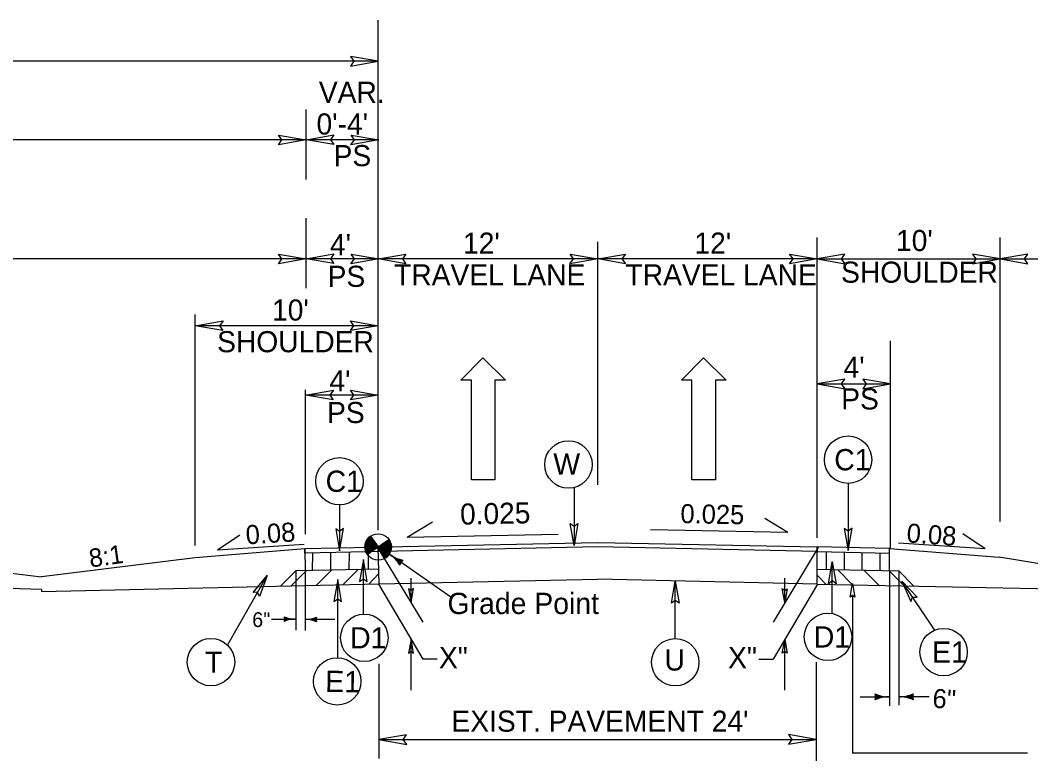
# Model space of a CAD drawing. Extents: x 2176024 to 2177225, y 75947 to 76635.
# Drawn here: x 2177049.6 to 2177104.9, y 76542.3 to 76582.8 of the extents above; entities that cross this region are included whole.
import ezdxf

# ---------------------------------------------------------------- set-up
doc = ezdxf.new("R2010")
doc.units = 0
for name, color, linetype in [('Exist XS Ground Line', 7, 'Continuous'), ('Old_Level_1', 7, 'Continuous'), ('Old_Level_11', 7, 'Continuous'), ('Old_Level_4', 7, 'Continuous'), ('Prop Dimension', 7, 'Continuous'), ('Typical Curb CELL', 7, 'Continuous'), ('Typical Grade Point Symbol CELL', 7, 'Continuous'), ('Typical Pavement Slope CELL', 7, 'Continuous'), ('Typical Pavement Slope Information CELL', 7, 'Continuous'), ('Typical Shoulder Slope CELL', 7, 'Continuous'), ('Typical Slope Point Local CELL', 7, 'Continuous'), ('Typical Terminator CELL', 7, 'Continuous'), ('Typical Text General CELL', 7, 'Continuous')]:
    doc.layers.add(name, color=color, linetype=linetype)

msp = doc.modelspace()

# ---------------------------------------------------------------- linework, layer by layer
at = {"layer": 'Exist XS Ground Line'}
for p in [(2177069.265, 76551.981), (2177093.221, 76551.969)]:
    msp.add_line(p, (2177081.227, 76552.231), dxfattribs=at)
at = {"layer": 'Old_Level_1'}
for p, q in [((2177065.623, 76552.698), (2177065.637, 76553.667)), ((2177066.62, 76552.722), (2177066.634, 76553.68)), ((2177067.635, 76552.744), (2177067.649, 76553.699)), ((2177068.681, 76552.775), (2177068.695, 76553.726)), ((2177093.726, 76552.759), (2177093.718, 76553.738)), ((2177094.715, 76552.74), (2177094.707, 76553.714)), ((2177095.672, 76552.708), (2177095.664, 76553.686)), ((2177096.661, 76552.687), (2177096.653, 76553.67)), ((2177064.445, 76551.858), (2177065.272, 76552.686)), ((2177065.853, 76551.914), (2177066.658, 76552.719)), ((2177067.295, 76551.943), (2177068.122, 76552.77)), ((2177095.143, 76551.933), (2177094.334, 76552.742)), ((2177096.614, 76551.876), (2177095.778, 76552.712)), ((2177097.972, 76551.871), (2177097.169, 76552.674)), ((2177068.709, 76551.969), (2177069.235, 76552.523)), ((2177093.713, 76551.95), (2177093.227, 76552.436))]:
    msp.add_line(p, q, dxfattribs=at)
at = {"layer": 'Old_Level_11'}
for p, q in [((2177079.924, 76557.205), (2177079.924, 76554.072)), ((2177094.903, 76557.467), (2177094.903, 76553.807)), ((2177067.1, 76556.289), (2177067.1, 76553.789)), ((2177068.413, 76550.33), (2177068.413, 76553.308)), ((2177073.192, 76551.258), (2177069.846, 76553.591)), ((2177064.718, 76552.686), (2177064.718, 76549.459)), ((2177065.218, 76552.663), (2177065.217, 76549.436)), ((2177094.029, 76550.372), (2177094.029, 76553.206)), ((2177097.17, 76552.676), (2177097.17, 76545.308)), ((2177097.67, 76552.716), (2177097.67, 76545.35)), ((2177060.977, 76548.639), (2177063.151, 76552.443)), ((2177067.002, 76547.947), (2177067.002, 76552.216)), ((2177085.454, 76548.994), (2177085.454, 76552.127)), ((2177099.642, 76549.455), (2177097.84, 76552.13)), ((2177063.385, 76550.06), (2177064.718, 76550.059)), ((2177066.856, 76550.037), (2177065.217, 76550.037)), ((2177095.57, 76545.808), (2177097.17, 76545.808)), ((2177099.337, 76545.812), (2177097.67, 76545.812))]:
    msp.add_line(p, q, dxfattribs=at)
for points in [[(2177066.893, 76554.989), (2177067.1, 76553.789), (2177067.313, 76554.996), (2177067.1, 76554.842)], [(2177080.13, 76555.272), (2177079.924, 76554.072), (2177079.71, 76555.278), (2177079.924, 76555.125)], [(2177094.697, 76555.007), (2177094.903, 76553.807), (2177095.117, 76555.014), (2177094.903, 76554.861)], [(2177068.619, 76552.108), (2177068.413, 76553.308), (2177068.199, 76552.101), (2177068.413, 76552.254)], [(2177093.838, 76551.99), (2177094.035, 76553.191), (2177094.258, 76551.986), (2177094.044, 76552.138)], [(2177062.376, 76551.504), (2177063.151, 76552.443), (2177062.737, 76551.29), (2177062.628, 76551.529)], [(2177067.209, 76551.016), (2177067.002, 76552.216), (2177066.789, 76551.01), (2177067.002, 76551.163)], [(2177085.247, 76550.927), (2177085.454, 76552.127), (2177085.667, 76550.92), (2177085.454, 76551.073)], [(2177098.682, 76551.251), (2177097.84, 76552.13), (2177098.337, 76551.011), (2177098.428, 76551.257)]]:
    msp.add_lwpolyline(points, close=True, dxfattribs=at)
for centre in [(2177094.903, 76558.763), (2177079.618, 76558.501), (2177067.1, 76557.585), (2177068.458, 76549.034), (2177093.803, 76549.082), (2177100.124, 76548.252), (2177060.078, 76547.705), (2177085.454, 76547.698), (2177066.976, 76546.651)]:
    msp.add_circle(centre, 1.296, dxfattribs=at)
for centre, radius, start, end in [((2177070.962, 76555.148), 1.915, 234.353, 258.6304), ((2177068.772, 76552.006), 1.915, 31.5997, 55.8772), ((2177070.962, 76555.148), 1.942, 244.6515, 257.9259), ((2177068.772, 76552.006), 1.942, 32.3043, 45.5787), ((2177070.962, 76555.148), 1.969, 248.5038, 257.3456), ((2177068.772, 76552.006), 1.969, 32.8846, 41.7264), ((2177070.962, 76555.148), 1.995, 251.4121, 256.8651), ((2177068.772, 76552.006), 1.995, 33.3651, 38.818), ((2177070.837, 76552.9), 0.448, 124.3493, 165.8809), ((2177070.962, 76555.148), 2.022, 253.8239, 256.468), ((2177068.772, 76552.006), 2.022, 33.7622, 36.4062), ((2177063.751, 76550.06), 0.359, 339.2311, 20.7627), ((2177064.698, 76551.592), 1.532, 246.4815, 270.759), ((2177064.697, 76548.527), 1.532, 89.2348, 113.5122), ((2177064.698, 76551.592), 1.554, 247.1861, 260.4605), ((2177064.697, 76548.527), 1.554, 99.5333, 112.8077), ((2177064.698, 76551.592), 1.575, 247.7664, 256.6082), ((2177064.697, 76548.527), 1.575, 103.3856, 112.2274), ((2177064.698, 76551.592), 1.596, 248.2469, 253.6998), ((2177064.697, 76548.527), 1.596, 106.2939, 111.7469), ((2177064.698, 76551.592), 1.618, 248.644, 251.2881), ((2177064.697, 76548.527), 1.618, 108.7057, 111.3498), ((2177065.238, 76551.569), 1.532, 269.2349, 293.5124), ((2177065.238, 76548.505), 1.532, 66.4817, 90.7591), ((2177065.238, 76551.569), 1.554, 279.5334, 292.8078), ((2177065.238, 76548.505), 1.554, 67.1862, 80.4606), ((2177065.238, 76551.569), 1.575, 283.3857, 292.2275), ((2177065.238, 76548.505), 1.575, 67.7665, 76.6083), ((2177065.238, 76551.569), 1.596, 286.2941, 291.747), ((2177065.238, 76548.505), 1.596, 68.247, 73.7), ((2177065.238, 76551.569), 1.618, 288.7059, 291.3499), ((2177065.238, 76548.505), 1.618, 68.6441, 71.2882), ((2177066.184, 76550.037), 0.359, 159.2312, 200.7628), ((2177095.961, 76545.808), 0.448, 339.2339, 20.7656), ((2177097.145, 76547.723), 1.915, 246.4844, 270.7618), ((2177097.145, 76543.893), 1.915, 89.2377, 113.5151), ((2177097.145, 76547.723), 1.942, 247.1889, 260.4633), ((2177097.145, 76543.893), 1.942, 99.5361, 112.8105), ((2177097.145, 76547.723), 1.969, 247.7692, 256.611), ((2177097.145, 76543.893), 1.969, 103.3884, 112.2302), ((2177097.145, 76547.723), 1.995, 248.2497, 253.7027), ((2177097.145, 76543.893), 1.995, 106.2968, 111.7497), ((2177097.145, 76547.723), 2.022, 248.6468, 251.2909), ((2177097.145, 76543.893), 2.022, 108.7086, 111.3527), ((2177097.696, 76547.727), 1.915, 269.2378, 293.5152), ((2177097.696, 76543.896), 1.915, 66.4845, 90.7619), ((2177097.696, 76547.727), 1.942, 279.5362, 292.8107), ((2177097.696, 76543.896), 1.942, 67.189, 80.4635), ((2177097.696, 76547.727), 1.969, 283.3885, 292.2304), ((2177097.696, 76543.896), 1.969, 67.7693, 76.6112), ((2177097.696, 76547.727), 1.995, 286.2969, 291.7498), ((2177097.696, 76543.896), 1.995, 68.2499, 73.7028), ((2177097.696, 76547.727), 2.022, 288.7087, 291.3528), ((2177097.696, 76543.896), 2.022, 68.6469, 71.291), ((2177098.879, 76545.812), 0.448, 159.234, 200.7657)]:
    msp.add_arc(centre, radius, start, end, dxfattribs=at)
at = {"layer": 'Old_Level_4'}
for p, q in [((2177073.733, 76563.101), (2177074.936, 76564.323)), ((2177074.936, 76564.323), (2177076.177, 76563.101)), ((2177085.788, 76563.101), (2177086.991, 76564.323)), ((2177086.991, 76564.323), (2177088.232, 76563.101)), ((2177074.315, 76563.101), (2177073.733, 76563.101)), ((2177074.315, 76557.669), (2177074.315, 76563.101)), ((2177076.177, 76563.101), (2177075.595, 76563.101)), ((2177075.595, 76563.101), (2177075.595, 76557.669)), ((2177086.37, 76563.101), (2177085.788, 76563.101)), ((2177086.37, 76557.669), (2177086.37, 76563.101)), ((2177088.232, 76563.101), (2177087.65, 76563.101)), ((2177087.65, 76563.101), (2177087.65, 76557.669)), ((2177075.595, 76557.669), (2177074.315, 76557.669)), ((2177087.65, 76557.669), (2177086.37, 76557.669))]:
    msp.add_line(p, q, dxfattribs=at)
at = {"layer": 'Prop Dimension'}
for p, q in [((2177069.218, 76554.916), (2177069.218, 76582.77)), ((2177069.218, 76580.525), (2177009.218, 76580.525)), ((2177065.278, 76574.07), (2177065.278, 76577.887)), ((2177065.278, 76576.236), (2177013.218, 76576.241)), ((2177069.248, 76576.236), (2177065.248, 76576.236)), ((2177065.278, 76568.14), (2177065.278, 76571.957)), ((2177093.218, 76554.486), (2177093.218, 76570.892)), ((2177103.218, 76555.385), (2177103.218, 76570.892)), ((2177081.218, 76557.394), (2177081.218, 76570.666)), ((2177065.248, 76569.734), (2177013.248, 76569.728)), ((2177069.248, 76569.734), (2177065.248, 76569.734)), ((2177081.218, 76569.728), (2177069.218, 76569.728)), ((2177093.218, 76569.728), (2177081.218, 76569.728)), ((2177093.218, 76569.728), (2177103.218, 76569.728)), ((2177103.218, 76569.728), (2177121.218, 76569.728)), ((2177059.218, 76554.067), (2177059.218, 76566.691)), ((2177069.218, 76566.082), (2177059.218, 76566.082)), ((2177097.218, 76553.891), (2177097.218, 76565.255)), ((2177093.218, 76562.899), (2177097.218, 76562.899)), ((2177065.248, 76554.702), (2177065.248, 76562.575)), ((2177069.218, 76562.293), (2177065.248, 76562.293)), ((2177069.182, 76553.97), (2177071.652, 76549.888)), ((2177093.272, 76553.97), (2177090.801, 76549.888)), ((2177071.015, 76550.963), (2177071.015, 76552.291)), ((2177091.438, 76550.963), (2177091.438, 76552.291)), ((2177069.227, 76551.969), (2177071.652, 76547.874)), ((2177093.227, 76551.969), (2177090.801, 76547.874)), ((2177095.145, 76551.375), (2177095.145, 76542.739)), ((2177071.015, 76546.173), (2177071.015, 76548.949)), ((2177091.438, 76546.173), (2177091.438, 76548.949)), ((2177072.432, 76547.874), (2177071.652, 76547.874)), ((2177090.021, 76547.874), (2177090.801, 76547.874)), ((2177093.161, 76547.698), (2177093.161, 76542.315)), ((2177069.257, 76547.609), (2177069.257, 76542.448)), ((2177069.257, 76543.474), (2177093.161, 76543.474)), ((2177104.713, 76542.739), (2177095.145, 76542.739))]:
    msp.add_line(p, q, dxfattribs=at)
at = {"layer": 'Typical Curb CELL'}
for p, q in [((2177069.265, 76551.981), (2177069.215, 76553.995)), ((2177093.221, 76551.969), (2177093.221, 76553.995)), ((2177097.17, 76552.676), (2177097.17, 76553.913)), ((2177050.807, 76551.67), (2177022.809, 76552.543)), ((2177050.807, 76551.568), (2177069.265, 76551.981))]:
    msp.add_line(p, q, dxfattribs=at)
at = {"layer": 'Typical Grade Point Symbol CELL'}
for p, q in [((2177068.803, 76554.587), (2177069.215, 76553.995)), ((2177069.215, 76553.995), (2177069.807, 76554.407)), ((2177068.622, 76553.585), (2177069.215, 76553.995)), ((2177069.215, 76553.995), (2177068.622, 76553.585)), ((2177069.627, 76553.403), (2177069.215, 76553.995))]:
    msp.add_line(p, q, dxfattribs=at)
for points in [[(2177068.97, 76554.347), (2177068.494, 76554.016)], [(2177068.978, 76554.336), (2177068.494, 76553.999)], [(2177068.986, 76554.324), (2177068.494, 76553.982)], [(2177068.962, 76554.359), (2177068.495, 76554.034)], [(2177068.953, 76554.371), (2177068.496, 76554.053)], [(2177068.945, 76554.383), (2177068.498, 76554.072)], [(2177068.937, 76554.395), (2177068.5, 76554.091)], [(2177068.929, 76554.407), (2177068.503, 76554.11)], [(2177068.92, 76554.418), (2177068.506, 76554.13)], [(2177068.912, 76554.43), (2177068.511, 76554.151)], [(2177068.904, 76554.442), (2177068.516, 76554.172)], [(2177068.896, 76554.454), (2177068.522, 76554.194)], [(2177068.887, 76554.466), (2177068.528, 76554.216)], [(2177068.879, 76554.477), (2177068.536, 76554.239)], [(2177068.871, 76554.489), (2177068.545, 76554.262)], [(2177068.863, 76554.501), (2177068.555, 76554.287)], [(2177068.854, 76554.513), (2177068.568, 76554.314)], [(2177068.846, 76554.525), (2177068.582, 76554.341)], [(2177068.838, 76554.537), (2177068.599, 76554.37)], [(2177068.83, 76554.549), (2177068.618, 76554.401)], [(2177068.821, 76554.56), (2177068.645, 76554.438)], [(2177068.813, 76554.572), (2177068.679, 76554.479)], [(2177068.805, 76554.584), (2177068.741, 76554.539)], [(2177069.81, 76554.401), (2177069.81, 76554.401), (2177069.219, 76553.99)], [(2177069.819, 76554.39), (2177069.227, 76553.978)], [(2177069.825, 76554.377), (2177069.235, 76553.966)], [(2177069.834, 76554.365), (2177069.243, 76553.954)], [(2177069.841, 76554.352), (2177069.252, 76553.942)], [(2177069.848, 76554.34), (2177069.26, 76553.931)], [(2177069.854, 76554.327), (2177069.268, 76553.919)], [(2177068.994, 76554.312), (2177068.495, 76553.964)], [(2177069.003, 76554.3), (2177068.495, 76553.947)], [(2177069.011, 76554.288), (2177068.497, 76553.93)], [(2177069.019, 76554.276), (2177068.499, 76553.914)], [(2177069.027, 76554.265), (2177068.5, 76553.898)], [(2177069.036, 76554.253), (2177068.503, 76553.882)], [(2177069.044, 76554.241), (2177068.506, 76553.867)], [(2177069.052, 76554.229), (2177068.509, 76553.851)], [(2177069.06, 76554.217), (2177068.512, 76553.836)], [(2177069.069, 76554.205), (2177068.515, 76553.82)], [(2177069.077, 76554.194), (2177068.519, 76553.806)], [(2177069.085, 76554.182), (2177068.524, 76553.791)], [(2177069.093, 76554.17), (2177068.528, 76553.776)], [(2177069.101, 76554.158), (2177068.534, 76553.763)], [(2177069.11, 76554.146), (2177068.538, 76553.748)], [(2177069.118, 76554.134), (2177068.543, 76553.735)], [(2177069.126, 76554.122), (2177068.549, 76553.721)], [(2177069.134, 76554.111), (2177068.555, 76553.707)], [(2177069.143, 76554.099), (2177068.56, 76553.694)], [(2177069.151, 76554.087), (2177068.567, 76553.681)], [(2177069.159, 76554.075), (2177068.573, 76553.667)], [(2177069.167, 76554.063), (2177068.58, 76553.654)], [(2177069.176, 76554.052), (2177068.587, 76553.642)], [(2177069.184, 76554.04), (2177068.593, 76553.629)], [(2177069.192, 76554.028), (2177068.602, 76553.617)], [(2177069.2, 76554.016), (2177068.609, 76553.604)], [(2177069.209, 76554.004), (2177068.617, 76553.592), (2177068.617, 76553.592)], [(2177069.861, 76554.314), (2177069.276, 76553.907)], [(2177069.868, 76554.301), (2177069.284, 76553.895)], [(2177069.874, 76554.288), (2177069.293, 76553.883)], [(2177069.879, 76554.274), (2177069.301, 76553.871)], [(2177069.885, 76554.26), (2177069.309, 76553.86)], [(2177069.891, 76554.247), (2177069.317, 76553.848)], [(2177069.895, 76554.232), (2177069.326, 76553.836)], [(2177069.901, 76554.218), (2177069.334, 76553.824)], [(2177069.905, 76554.204), (2177069.342, 76553.812)], [(2177069.909, 76554.189), (2177069.35, 76553.8)], [(2177069.914, 76554.175), (2177069.359, 76553.789)], [(2177069.916, 76554.159), (2177069.367, 76553.777)], [(2177069.919, 76554.144), (2177069.375, 76553.765)], [(2177069.922, 76554.128), (2177069.383, 76553.753)], [(2177069.925, 76554.113), (2177069.392, 76553.741)], [(2177069.928, 76554.097), (2177069.4, 76553.729)], [(2177069.93, 76554.081), (2177069.408, 76553.718)], [(2177069.932, 76554.064), (2177069.416, 76553.706)], [(2177069.933, 76554.048), (2177069.424, 76553.694)], [(2177069.935, 76554.032), (2177069.433, 76553.682)], [(2177069.935, 76554.014), (2177069.441, 76553.67)], [(2177069.936, 76553.997), (2177069.449, 76553.658)], [(2177069.935, 76553.979), (2177069.457, 76553.647)], [(2177069.935, 76553.961), (2177069.466, 76553.635)], [(2177069.934, 76553.943), (2177069.474, 76553.623)], [(2177069.932, 76553.924), (2177069.482, 76553.611)], [(2177069.93, 76553.905), (2177069.49, 76553.599)], [(2177069.927, 76553.886), (2177069.499, 76553.587)], [(2177069.924, 76553.866), (2177069.507, 76553.576)], [(2177069.92, 76553.846), (2177069.515, 76553.564)], [(2177069.915, 76553.825), (2177069.523, 76553.552)], [(2177069.909, 76553.803), (2177069.532, 76553.54)], [(2177069.903, 76553.781), (2177069.54, 76553.528)], [(2177069.895, 76553.758), (2177069.548, 76553.516)], [(2177069.886, 76553.734), (2177069.556, 76553.505)], [(2177069.876, 76553.71), (2177069.565, 76553.493)], [(2177069.865, 76553.684), (2177069.573, 76553.481)], [(2177069.852, 76553.658), (2177069.581, 76553.469)], [(2177069.835, 76553.628), (2177069.589, 76553.457)], [(2177069.816, 76553.597), (2177069.597, 76553.445)], [(2177069.791, 76553.563), (2177069.606, 76553.434)], [(2177069.759, 76553.522), (2177069.614, 76553.422)], [(2177069.706, 76553.468), (2177069.622, 76553.41)]]:
    msp.add_lwpolyline(points, dxfattribs=at)
msp.add_circle((2177069.215, 76553.996), 0.721, dxfattribs=at)
for start, end in [(124.8249, 214.8249), (304.8249, 34.8249)]:
    msp.add_arc((2177069.215, 76553.996), 0.721, start, end, dxfattribs=at)
at = {"layer": 'Typical Pavement Slope CELL'}
for p, q in [((2177065.216, 76553.912), (2177065.217, 76552.687)), ((2177137.17, 76547.766), (2177103.17, 76553.433)), ((2177064.718, 76552.686), (2177063.886, 76551.859)), ((2177097.67, 76552.683), (2177098.499, 76551.859)), ((2177093.221, 76551.969), (2177114.631, 76551.523))]:
    msp.add_line(p, q, dxfattribs=at)
at = {"layer": 'Typical Pavement Slope Information CELL'}
for p, q in [((2177091.61, 76554.782), (2177090.349, 76555.544)), ((2177070.798, 76554.536), (2177072.186, 76555.375)), ((2177091.61, 76554.782), (2177084.105, 76554.932)), ((2177060.431, 76553.842), (2177061.655, 76554.662)), ((2177070.798, 76554.536), (2177079.056, 76554.701)), ((2177102.396, 76553.895), (2177101.172, 76554.714)), ((2177060.431, 76553.842), (2177065.177, 76554.156)), ((2177102.396, 76553.895), (2177097.65, 76554.208))]:
    msp.add_line(p, q, dxfattribs=at)
at = {"layer": 'Typical Shoulder Slope CELL'}
for p, q in [((2177065.216, 76553.887), (2177059.216, 76553.407)), ((2177097.17, 76553.913), (2177103.17, 76553.433)), ((2177039.22, 76553.763), (2177050.807, 76552.356)), ((2177059.216, 76553.407), (2177050.807, 76552.356)), ((2177069.245, 76552.787), (2177064.718, 76552.686)), ((2177093.221, 76552.775), (2177097.67, 76552.683)), ((2177050.807, 76551.67), (2177050.807, 76551.568))]:
    msp.add_line(p, q, dxfattribs=at)
at = {"layer": 'Typical Slope Point Local CELL'}
for points in [[(2177065.216, 76553.912), (2177081.227, 76554.245), (2177093.221, 76553.995), (2177093.221, 76553.745), (2177081.227, 76553.995), (2177065.216, 76553.662)], [(2177097.17, 76553.913), (2177093.221, 76553.995), (2177093.221, 76553.745), (2177097.17, 76553.663)]]:
    msp.add_lwpolyline(points, close=True, dxfattribs=at)
at = {"layer": 'Typical Terminator CELL'}
for points in [[(2177067.709, 76580.265), (2177069.218, 76580.525), (2177067.7, 76580.793), (2177067.893, 76580.525)], [(2177063.768, 76576.496), (2177065.278, 76576.236), (2177063.76, 76575.967), (2177063.953, 76576.236)], [(2177066.788, 76575.976), (2177065.278, 76576.236), (2177066.796, 76576.504), (2177066.603, 76576.236)], [(2177067.738, 76576.496), (2177069.248, 76576.236), (2177067.73, 76575.967), (2177067.923, 76576.236)], [(2177063.768, 76569.994), (2177065.278, 76569.734), (2177063.76, 76569.465), (2177063.953, 76569.734)], [(2177066.788, 76569.474), (2177065.278, 76569.734), (2177066.796, 76570.002), (2177066.603, 76569.734)], [(2177067.738, 76569.994), (2177069.248, 76569.734), (2177067.73, 76569.465), (2177067.923, 76569.734)], [(2177070.728, 76569.468), (2177069.218, 76569.728), (2177070.736, 76569.997), (2177070.543, 76569.728)], [(2177079.709, 76569.988), (2177081.218, 76569.728), (2177079.7, 76569.46), (2177079.893, 76569.728)], [(2177082.728, 76569.468), (2177081.218, 76569.728), (2177082.736, 76569.997), (2177082.543, 76569.728)], [(2177091.709, 76569.988), (2177093.218, 76569.728), (2177091.7, 76569.46), (2177091.893, 76569.728)], [(2177094.728, 76569.988), (2177093.218, 76569.728), (2177094.736, 76569.46), (2177094.543, 76569.728)], [(2177101.709, 76569.468), (2177103.218, 76569.728), (2177101.7, 76569.997), (2177101.893, 76569.728)], [(2177104.728, 76569.988), (2177103.218, 76569.728), (2177104.736, 76569.46), (2177104.543, 76569.728)], [(2177060.728, 76565.822), (2177059.218, 76566.082), (2177060.736, 76566.351), (2177060.543, 76566.082)], [(2177067.709, 76566.342), (2177069.218, 76566.082), (2177067.7, 76565.814), (2177067.893, 76566.082)], [(2177094.728, 76563.159), (2177093.218, 76562.899), (2177094.736, 76562.631), (2177094.543, 76562.899)], [(2177095.709, 76562.639), (2177097.218, 76562.899), (2177095.7, 76563.168), (2177095.893, 76562.899)], [(2177066.758, 76562.033), (2177065.248, 76562.293), (2177066.766, 76562.561), (2177066.573, 76562.293)], [(2177067.709, 76562.553), (2177069.218, 76562.293), (2177067.7, 76562.024), (2177067.893, 76562.293)], [(2177070.883, 76551.717), (2177071.015, 76550.963), (2177071.147, 76551.722), (2177071.013, 76551.625)], [(2177091.571, 76551.717), (2177091.438, 76550.963), (2177091.306, 76551.722), (2177091.44, 76551.625)], [(2177095.015, 76551.252), (2177095.145, 76552.007), (2177095.279, 76551.248), (2177095.145, 76551.345)], [(2177071.147, 76548.195), (2177071.015, 76548.949), (2177070.883, 76548.19), (2177071.017, 76548.287)], [(2177091.306, 76548.195), (2177091.438, 76548.949), (2177091.57, 76548.19), (2177091.436, 76548.287)], [(2177070.766, 76543.734), (2177069.257, 76543.474), (2177070.775, 76543.205), (2177070.582, 76543.474)], [(2177091.651, 76543.214), (2177093.161, 76543.474), (2177091.643, 76543.742), (2177091.836, 76543.474)]]:
    msp.add_lwpolyline(points, close=True, dxfattribs=at)

# ---------------------------------------------------------------- texts
at = {"layer": 'Old_Level_11'}
for s, height, rotation, p in [('C1', 1.16, 0.0003, (2177094.147, 76558.183)), ('W', 1.16, 0.0003, (2177078.791, 76557.943)), ('C1', 1.16, 0.0003, (2177066.344, 76557.005)), ('Grade Point', 1.16, 0.0002, (2177073.008, 76550.331)), ('6"', 0.8051, 358.8245, (2177062.324, 76549.629)), ('D1', 1.16, 0.0003, (2177067.685, 76548.454)), ('D1', 1.16, 0.0003, (2177093.03, 76548.502)), ('E1', 1.16, 0.0003, (2177099.496, 76547.672)), ('T', 1.16, 359.8567, (2177059.75, 76547.125)), ('U', 1.16, 0.0003, (2177084.867, 76547.244)), ('E1', 1.16, 358.8249, (2177066.314, 76546.084))]:
    msp.add_text(s, height=height, rotation=rotation, dxfattribs=at).set_placement(p)
for p in [(2177072.539, 76547.373), (2177088.344, 76547.373)]:
    msp.add_text('X"', height=1.1533, dxfattribs=at).set_placement(p)
at = {"layer": 'Typical Pavement Slope Information CELL'}
for s, height, rotation, p in [('0.025', 1.1475, 1.1457, (2177073.706, 76555.214)), ('0.025', 1.0429, 358.8543, (2177085.73, 76555.3)), ('0.08', 1.0429, 3.5795, (2177062.007, 76554.134)), ('0.08', 1.0429, 355.8928, (2177098.076, 76554.249)), ('6"', 1.0429, 355.8928, (2177099.488, 76545.219))]:
    msp.add_text(s, height=height, rotation=rotation, dxfattribs=at).set_placement(p)
at = {"layer": 'Typical Slope Point Local CELL'}
msp.add_text('8:1', height=1.0064, rotation=8.0589, dxfattribs=at).set_placement((2177053.483, 76552.868))
at = {"layer": 'Typical Text General CELL'}
for s, height, p in [('VAR. ', 1.1533, (2177065.974, 76578.257)), ("0'-4' ", 1.1533, (2177065.846, 76576.527)), ('PS', 1.1533, (2177066.778, 76574.797)), ("4'", 1.1533, (2177066.58, 76569.934)), ("12' ", 1.1533, (2177073.855, 76570.017)), ("12' ", 1.1533, (2177086.504, 76570.017)), ("10' ", 1.1533, (2177097.521, 76570.16)), ('PS', 1.1533, (2177066.451, 76568.204)), ('TRAVEL LANE', 1.15334, (2177070.085, 76568.287)), ('TRAVEL LANE', 1.15334, (2177082.734, 76568.287)), ('SHOULDER', 1.1533, (2177094.52, 76568.43)), ("10'", 1.1533, (2177063.414, 76566.363)), ('SHOULDER', 1.1533, (2177060.412, 76564.633)), ("4'", 1.1533, (2177094.656, 76563.237)), ("4'", 1.1533, (2177066.55, 76562.493)), ('PS', 1.1533, (2177094.527, 76561.507)), ('PS', 1.1533, (2177066.421, 76560.763)), ("EXIST. PAVEMENT 24'", 1.15334, (2177073.222, 76543.901))]:
    msp.add_text(s, height=height, dxfattribs=at).set_placement(p)

doc.saveas('drawing.dxf')
